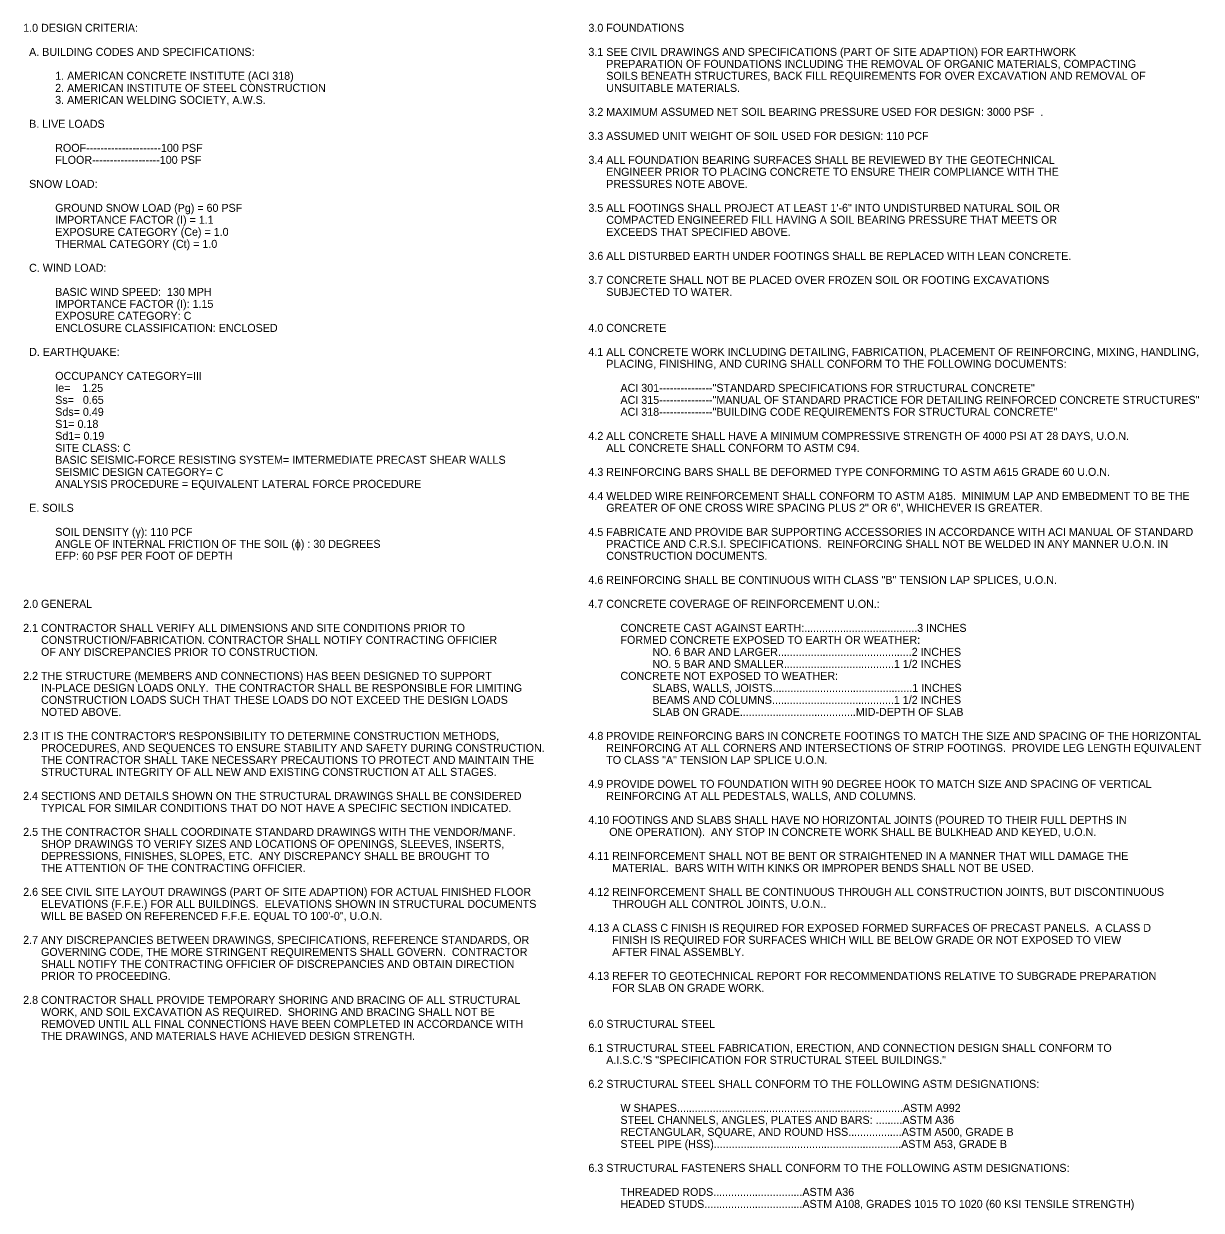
# Model space of a CAD drawing. Extents: x 0.17 to 2.69, y 0.12 to 1.68.
# Drawn here: x 0.174 to 1.707, y 0.137 to 1.682 of the extents above; entities that cross this region are included whole.
import ezdxf

# ---------------------------------------------------------------- set-up
doc = ezdxf.new("R2010")
doc.units = 0
doc.layers.add('G-ANNO-TEXT', color=7, linetype='Continuous')

msp = doc.modelspace()

# ---------------------------------------------------------------- texts
at = {"layer": 'G-ANNO-TEXT'}
for s, height, p in [('1.0 DESIGN CRITERIA:', 0.010417, (0.1733, 1.6713)), ('3.0 FOUNDATIONS', 0.010417, (0.909, 1.6713)), ('  A. BUILDING CODES AND SPECIFICATIONS:', 0.010417, (0.1733, 1.64)), ('3.1 SEE CIVIL DRAWINGS AND SPECIFICATIONS (PART OF SITE ADAPTION) FOR EARTHWORK ', 0.010417, (0.909, 1.64)), ('      PREPARATION OF FOUNDATIONS INCLUDING THE REMOVAL OF ORGANIC MATERIALS, COMPACTING', 0.010417, (0.909, 1.6244)), ('1. AMERICAN CONCRETE INSTITUTE (ACI 318)', 0.010417, (0.215, 1.6088)), ('      SOILS BENEATH STRUCTURES, BACK FILL REQUIREMENTS FOR OVER EXCAVATION AND REMOVAL OF ', 0.010417, (0.909, 1.6088)), ('2. AMERICAN INSTITUTE OF STEEL CONSTRUCTION', 0.010417, (0.215, 1.5931)), ('      UNSUITABLE MATERIALS.', 0.010417, (0.909, 1.5931)), ('3. AMERICAN WELDING SOCIETY, A.W.S.', 0.010417, (0.215, 1.5775)), ('3.2 MAXIMUM ASSUMED NET SOIL BEARING PRESSURE USED FOR DESIGN: 3000 PSF  . ', 0.010417, (0.909, 1.5619)), ('  B. LIVE LOADS', 0.010417, (0.1733, 1.5463)), ('3.3 ASSUMED UNIT WEIGHT OF SOIL USED FOR DESIGN: 110 PCF', 0.010417, (0.909, 1.5306)), ('ROOF---------------------100 PSF', 0.010417, (0.215, 1.515)), ('FLOOR-------------------100 PSF', 0.010417, (0.215, 1.4994)), ('3.4 ALL FOUNDATION BEARING SURFACES SHALL BE REVIEWED BY THE GEOTECHNICAL', 0.010417, (0.909, 1.4994)), ('      ENGINEER PRIOR TO PLACING CONCRETE TO ENSURE THEIR COMPLIANCE WITH THE ', 0.010417, (0.909, 1.4838)), ('  SNOW LOAD:', 0.010417, (0.1733, 1.4681)), ('      PRESSURES NOTE ABOVE.  ', 0.010417, (0.909, 1.4681)), ('GROUND SNOW LOAD (Pg) = 60 PSF', 0.010417, (0.215, 1.4369)), ('3.5 ALL FOOTINGS SHALL PROJECT AT LEAST 1\'-6" INTO UNDISTURBED NATURAL SOIL OR', 0.010417, (0.909, 1.4369)), ('IMPORTANCE FACTOR (I) = 1.1', 0.010417, (0.215, 1.4213)), ('      COMPACTED ENGINEERED FILL HAVING A SOIL BEARING PRESSURE THAT MEETS OR', 0.010417, (0.909, 1.4213)), ('EXPOSURE CATEGORY (Ce) = 1.0', 0.010417, (0.215, 1.4056)), ('      EXCEEDS THAT SPECIFIED ABOVE.', 0.010417, (0.909, 1.4056)), ('THERMAL CATEGORY (Ct) = 1.0', 0.010417, (0.215, 1.39)), ('3.6 ALL DISTURBED EARTH UNDER FOOTINGS SHALL BE REPLACED WITH LEAN CONCRETE.', 0.010417, (0.909, 1.3744)), ('  C. WIND LOAD:', 0.010417, (0.1733, 1.3588)), ('3.7 CONCRETE SHALL NOT BE PLACED OVER FROZEN SOIL OR FOOTING EXCAVATIONS ', 0.010417, (0.909, 1.3431)), ('BASIC WIND SPEED:  130 MPH', 0.010417, (0.215, 1.3275)), ('      SUBJECTED TO WATER. ', 0.010417, (0.909, 1.3275)), ('IMPORTANCE FACTOR (I): 1.15', 0.010417, (0.215, 1.3119)), ('EXPOSURE CATEGORY: C', 0.010417, (0.215, 1.2963)), ('ENCLOSURE CLASSIFICATION: ENCLOSED', 0.010417, (0.215, 1.2806)), ('4.0 CONCRETE', 0.010417, (0.909, 1.2806)), ('  D. EARTHQUAKE:', 0.010417, (0.1733, 1.2494)), ('4.1 ALL CONCRETE WORK INCLUDING DETAILING, FABRICATION, PLACEMENT OF REINFORCING, MIXING, HANDLING,', 0.010417, (0.909, 1.2494)), ('      PLACING, FINISHING, AND CURING SHALL CONFORM TO THE FOLLOWING DOCUMENTS:', 0.010417, (0.909, 1.2338)), ('OCCUPANCY CATEGORY=III', 0.010417, (0.215, 1.2181)), ('Ie=    1.25', 0.010417, (0.215, 1.2025)), ('ACI 301---------------"STANDARD SPECIFICATIONS FOR STRUCTURAL CONCRETE"', 0.010417, (0.9507, 1.2025)), ('Ss=   0.65', 0.01042, (0.215, 1.1869)), ('ACI 315---------------"MANUAL OF STANDARD PRACTICE FOR DETAILING REINFORCED CONCRETE STRUCTURES"', 0.010417, (0.9507, 1.1869)), ('Sds= 0.49', 0.01042, (0.215, 1.1713)), ('ACI 318---------------"BUILDING CODE REQUIREMENTS FOR STRUCTURAL CONCRETE"', 0.010417, (0.9507, 1.1713)), ('S1= 0.18', 0.01042, (0.215, 1.1556)), ('Sd1= 0.19', 0.01042, (0.215, 1.14)), ('4.2 ALL CONCRETE SHALL HAVE A MINIMUM COMPRESSIVE STRENGTH OF 4000 PSI AT 28 DAYS, U.O.N.', 0.010417, (0.909, 1.14)), ('SITE CLASS: C', 0.010417, (0.215, 1.1244)), ('      ALL CONCRETE SHALL CONFORM TO ASTM C94.', 0.010417, (0.909, 1.1244)), ('BASIC SEISMIC-FORCE RESISTING SYSTEM= IMTERMEDIATE PRECAST SHEAR WALLS', 0.010417, (0.215, 1.1088)), ('SEISMIC DESIGN CATEGORY= C', 0.010417, (0.215, 1.0931)), ('4.3 REINFORCING BARS SHALL BE DEFORMED TYPE CONFORMING TO ASTM A615 GRADE 60 U.O.N.', 0.010417, (0.909, 1.0931)), ('ANALYSIS PROCEDURE = EQUIVALENT LATERAL FORCE PROCEDURE ', 0.010417, (0.215, 1.0775)), ('4.4 WELDED WIRE REINFORCEMENT SHALL CONFORM TO ASTM A185.  MINIMUM LAP AND EMBEDMENT TO BE THE', 0.010417, (0.909, 1.0619)), ('  E. SOILS', 0.01042, (0.1733, 1.0463)), ('      GREATER OF ONE CROSS WIRE SPACING PLUS 2" OR 6", WHICHEVER IS GREATER.', 0.010417, (0.909, 1.0463)), ('SOIL DENSITY (γ): 110 PCF', 0.010417, (0.215, 1.015)), ('4.5 FABRICATE AND PROVIDE BAR SUPPORTING ACCESSORIES IN ACCORDANCE WITH ACI MANUAL OF STANDARD', 0.010417, (0.909, 1.015)), ('ANGLE OF INTERNAL FRICTION OF THE SOIL (ϕ) : 30 DEGREES', 0.010417, (0.215, 0.9994)), ('      PRACTICE AND C.R.S.I. SPECIFICATIONS.  REINFORCING SHALL NOT BE WELDED IN ANY MANNER U.O.N. IN', 0.010417, (0.909, 0.9994)), ('EFP: 60 PSF PER FOOT OF DEPTH', 0.010417, (0.215, 0.9838)), ('      CONSTRUCTION DOCUMENTS.', 0.010417, (0.909, 0.9838)), ('4.6 REINFORCING SHALL BE CONTINUOUS WITH CLASS "B" TENSION LAP SPLICES, U.O.N.', 0.010417, (0.909, 0.9525)), ('2.0 GENERAL ', 0.010417, (0.1733, 0.9213)), ('4.7 CONCRETE COVERAGE OF REINFORCEMENT U.ON.:', 0.010417, (0.909, 0.9213)), ('2.1 CONTRACTOR SHALL VERIFY ALL DIMENSIONS AND SITE CONDITIONS PRIOR TO ', 0.010417, (0.1733, 0.89)), ('CONCRETE CAST AGAINST EARTH:......................................3 INCHES', 0.010417, (0.9507, 0.89)), ('      CONSTRUCTION/FABRICATION. CONTRACTOR SHALL NOTIFY CONTRACTING OFFICIER', 0.010417, (0.1733, 0.8744)), ('FORMED CONCRETE EXPOSED TO EARTH OR WEATHER:', 0.010417, (0.9507, 0.8744)), ('      OF ANY DISCREPANCIES PRIOR TO CONSTRUCTION.', 0.010417, (0.1733, 0.8588)), ('NO. 6 BAR AND LARGER.............................................2 INCHES', 0.010417, (0.9923, 0.8588)), ('NO. 5 BAR AND SMALLER.....................................1 1/2 INCHES', 0.010417, (0.9923, 0.8431)), ('2.2 THE STRUCTURE (MEMBERS AND CONNECTIONS) HAS BEEN DESIGNED TO SUPPORT', 0.010417, (0.1733, 0.8275)), ('CONCRETE NOT EXPOSED TO WEATHER:', 0.010417, (0.9507, 0.8275)), ('      IN-PLACE DESIGN LOADS ONLY.  THE CONTRACTOR SHALL BE RESPONSIBLE FOR LIMITING ', 0.010417, (0.1733, 0.8119)), ('SLABS, WALLS, JOISTS...............................................1 INCHES', 0.010417, (0.9923, 0.8119)), ('      CONSTRUCTION LOADS SUCH THAT THESE LOADS DO NOT EXCEED THE DESIGN LOADS', 0.010417, (0.1733, 0.7963)), ('BEAMS AND COLUMNS.........................................1 1/2 INCHES', 0.010417, (0.9923, 0.7963)), ('      NOTED ABOVE. ', 0.010417, (0.1733, 0.7806)), ('SLAB ON GRADE.......................................MID-DEPTH OF SLAB', 0.010417, (0.9923, 0.7806)), ("2.3 IT IS THE CONTRACTOR'S RESPONSIBILITY TO DETERMINE CONSTRUCTION METHODS,", 0.010417, (0.1733, 0.7494)), ('4.8 PROVIDE REINFORCING BARS IN CONCRETE FOOTINGS TO MATCH THE SIZE AND SPACING OF THE HORIZONTAL ', 0.010417, (0.909, 0.7494)), ('      PROCEDURES, AND SEQUENCES TO ENSURE STABILITY AND SAFETY DURING CONSTRUCTION.  ', 0.010417, (0.1733, 0.7338)), ('      REINFORCING AT ALL CORNERS AND INTERSECTIONS OF STRIP FOOTINGS.  PROVIDE LEG LENGTH EQUIVALENT', 0.010417, (0.909, 0.7338)), ('      THE CONTRACTOR SHALL TAKE NECESSARY PRECAUTIONS TO PROTECT AND MAINTAIN THE ', 0.010417, (0.1733, 0.7181)), ('      TO CLASS "A" TENSION LAP SPLICE U.O.N.', 0.010417, (0.909, 0.7181)), ('      STRUCTURAL INTEGRITY OF ALL NEW AND EXISTING CONSTRUCTION AT ALL STAGES.  ', 0.010417, (0.1733, 0.7025)), ('4.9 PROVIDE DOWEL TO FOUNDATION WITH 90 DEGREE HOOK TO MATCH SIZE AND SPACING OF VERTICAL', 0.010417, (0.909, 0.6869)), ('2.4 SECTIONS AND DETAILS SHOWN ON THE STRUCTURAL DRAWINGS SHALL BE CONSIDERED ', 0.010417, (0.1733, 0.6713)), ('      REINFORCING AT ALL PEDESTALS, WALLS, AND COLUMNS.', 0.010417, (0.909, 0.6713)), ('      TYPICAL FOR SIMILAR CONDITIONS THAT DO NOT HAVE A SPECIFIC SECTION INDICATED.  ', 0.010417, (0.1733, 0.6556)), ('4.10 FOOTINGS AND SLABS SHALL HAVE NO HORIZONTAL JOINTS (POURED TO THEIR FULL DEPTHS IN ', 0.010417, (0.909, 0.64)), ('2.5 THE CONTRACTOR SHALL COORDINATE STANDARD DRAWINGS WITH THE VENDOR/MANF.', 0.010417, (0.1733, 0.6244)), ('       ONE OPERATION).  ANY STOP IN CONCRETE WORK SHALL BE BULKHEAD AND KEYED, U.O.N.', 0.010417, (0.909, 0.6244)), ('      SHOP DRAWINGS TO VERIFY SIZES AND LOCATIONS OF OPENINGS, SLEEVES, INSERTS,', 0.010417, (0.1733, 0.6088)), ('      DEPRESSIONS, FINISHES, SLOPES, ETC.  ANY DISCREPANCY SHALL BE BROUGHT TO', 0.010417, (0.1733, 0.5931)), ('4.11 REINFORCEMENT SHALL NOT BE BENT OR STRAIGHTENED IN A MANNER THAT WILL DAMAGE THE', 0.010417, (0.909, 0.5931)), ('      THE ATTENTION OF THE CONTRACTING OFFICIER.', 0.010417, (0.1733, 0.5775)), ('        MATERIAL.  BARS WITH WITH KINKS OR IMPROPER BENDS SHALL NOT BE USED.', 0.010417, (0.909, 0.5775)), ('2.6 SEE CIVIL SITE LAYOUT DRAWINGS (PART OF SITE ADAPTION) FOR ACTUAL FINISHED FLOOR  ', 0.010417, (0.1733, 0.5463)), ('4.12 REINFORCEMENT SHALL BE CONTINUOUS THROUGH ALL CONSTRUCTION JOINTS, BUT DISCONTINUOUS', 0.010417, (0.909, 0.5463)), ('      ELEVATIONS (F.F.E.) FOR ALL BUILDINGS.  ELEVATIONS SHOWN IN STRUCTURAL DOCUMENTS', 0.010417, (0.1733, 0.5306)), ('        THROUGH ALL CONTROL JOINTS, U.O.N..', 0.010417, (0.909, 0.5306)), ('      WILL BE BASED ON REFERENCED F.F.E. EQUAL TO 100\'-0", U.O.N.', 0.010417, (0.1733, 0.515)), ('4.13 A CLASS C FINISH IS REQUIRED FOR EXPOSED FORMED SURFACES OF PRECAST PANELS.  A CLASS D ', 0.010417, (0.909, 0.4994)), ('2.7 ANY DISCREPANCIES BETWEEN DRAWINGS, SPECIFICATIONS, REFERENCE STANDARDS, OR ', 0.010417, (0.1733, 0.4838)), ('        FINISH IS REQUIRED FOR SURFACES WHICH WILL BE BELOW GRADE OR NOT EXPOSED TO VIEW ', 0.010417, (0.909, 0.4838)), ('      GOVERNING CODE, THE MORE STRINGENT REQUIREMENTS SHALL GOVERN.  CONTRACTOR ', 0.010417, (0.1733, 0.4681)), ('        AFTER FINAL ASSEMBLY.', 0.010417, (0.909, 0.4681)), ('      SHALL NOTIFY THE CONTRACTING OFFICIER OF DISCREPANCIES AND OBTAIN DIRECTION ', 0.010417, (0.1733, 0.4525)), ('      PRIOR TO PROCEEDING.         ', 0.010417, (0.1733, 0.4369)), ('4.13 REFER TO GEOTECHNICAL REPORT FOR RECOMMENDATIONS RELATIVE TO SUBGRADE PREPARATION', 0.010417, (0.909, 0.4369)), ('        FOR SLAB ON GRADE WORK.    ', 0.010417, (0.909, 0.4213)), ('2.8 CONTRACTOR SHALL PROVIDE TEMPORARY SHORING AND BRACING OF ALL STRUCTURAL ', 0.010417, (0.1733, 0.4056)), ('      WORK, AND SOIL EXCAVATION AS REQUIRED.  SHORING AND BRACING SHALL NOT BE ', 0.010417, (0.1733, 0.39)), ('      REMOVED UNTIL ALL FINAL CONNECTIONS HAVE BEEN COMPLETED IN ACCORDANCE WITH', 0.010417, (0.1733, 0.3744)), ('6.0 STRUCTURAL STEEL', 0.010417, (0.909, 0.3744)), ('      THE DRAWINGS, AND MATERIALS HAVE ACHIEVED DESIGN STRENGTH.', 0.010417, (0.1733, 0.3588)), ('6.1 STRUCTURAL STEEL FABRICATION, ERECTION, AND CONNECTION DESIGN SHALL CONFORM TO ', 0.010417, (0.909, 0.3431)), ('      A.I.S.C.\'S "SPECIFICATION FOR STRUCTURAL STEEL BUILDINGS." ', 0.010417, (0.909, 0.3275)), ('6.2 STRUCTURAL STEEL SHALL CONFORM TO THE FOLLOWING ASTM DESIGNATIONS:', 0.010417, (0.909, 0.2963)), ('W SHAPES............................................................................ASTM A992', 0.010417, (0.9507, 0.265)), ('STEEL CHANNELS, ANGLES, PLATES AND BARS: .........ASTM A36', 0.010417, (0.9507, 0.2494)), ('RECTANGULAR, SQUARE, AND ROUND HSS..................ASTM A500, GRADE B', 0.010417, (0.9507, 0.2338)), ('STEEL PIPE (HSS)...............................................................ASTM A53, GRADE B ', 0.010417, (0.9507, 0.2181)), ('6.3 STRUCTURAL FASTENERS SHALL CONFORM TO THE FOLLOWING ASTM DESIGNATIONS:', 0.010417, (0.909, 0.1869)), ('THREADED RODS..............................ASTM A36', 0.010417, (0.9507, 0.1556)), ('HEADED STUDS.................................ASTM A108, GRADES 1015 TO 1020 (60 KSI TENSILE STRENGTH)', 0.0104167, (0.9507, 0.14))]:
    msp.add_text(s, height=height, dxfattribs=at).set_placement(p)

doc.saveas('drawing.dxf')
